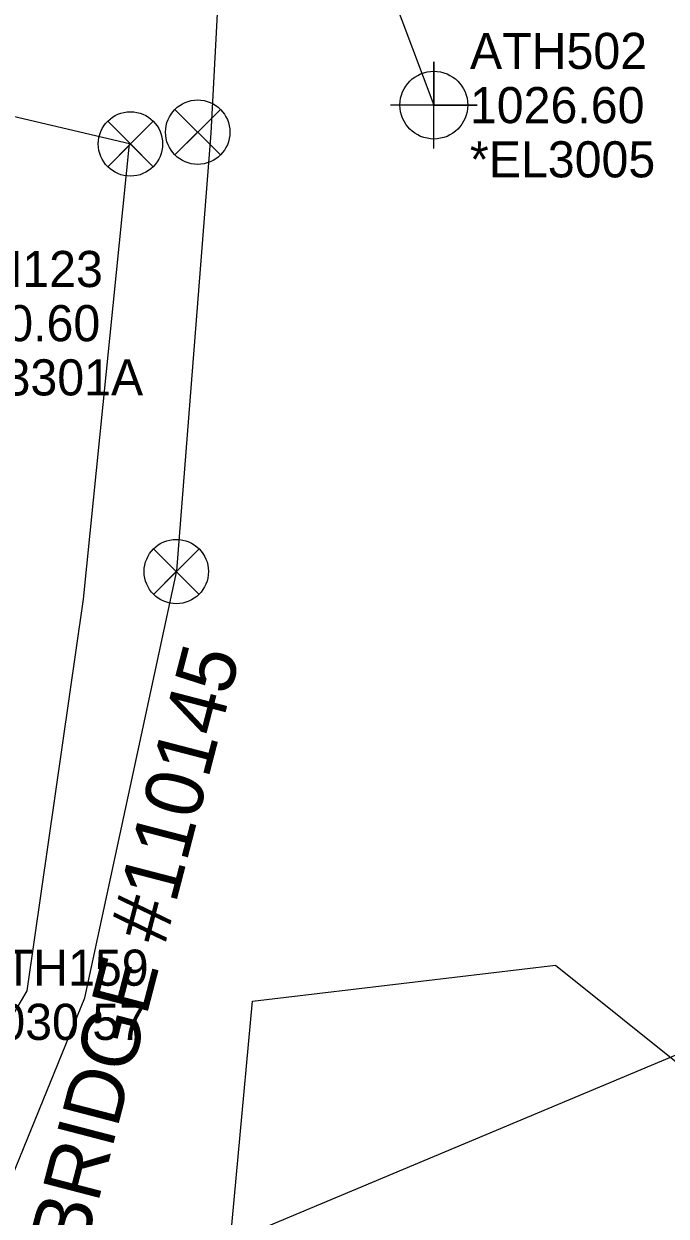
# Model space of a CAD drawing. Extents: x 1212084 to 1214478, y 765637 to 767408.
# Drawn here: x 1213372.2 to 1213416.6, y 766500.6 to 766583.1 of the extents above; entities that cross this region are included whole.
import ezdxf

# ---------------------------------------------------------------- set-up
doc = ezdxf.new("R2010")
doc.units = 0
for name, color, linetype in [('Exist Guardrail Cogo Comment', 7, 'Continuous'), ('Exist Guardrail Cogo Elevation', 7, 'Continuous'), ('Exist Guardrail Cogo Number', 7, 'Continuous'), ('Exist Roads Soil', 7, 'Continuous'), ('Exist Roads Soil Cogo Comment', 7, 'Continuous'), ('Exist Roads Soil Cogo Elevation', 7, 'Continuous'), ('Exist Roads Soil Cogo Number', 7, 'Continuous'), ('Exist Roads Soil Cogo Point CELL', 7, 'Continuous'), ('Exist Structure Major Deck Tunnel Box Culvert Text', 7, 'Continuous'), ('Exist Utilities Other Located Object Text', 7, 'Continuous'), ('Exist Utilities Telephone Pole Cogo Elevation', 7, 'Continuous'), ('Exist Utilities Telephone Pole Cogo Number', 7, 'Continuous'), ('Exist Utilities Water UG Line SUE LOS B', 7, 'Continuous'), ('Exist Utilities Water Valve CELL', 7, 'Continuous'), ('Exist Vegetation Woods Line', 7, 'Continuous')]:
    doc.layers.add(name, color=color, linetype=linetype)

msp = doc.modelspace()

# ---------------------------------------------------------------- linework, layer by layer
at = {"layer": 'Exist Roads Soil'}
msp.add_lwpolyline([(1213379.085, 766618.493), (1213384.449, 766620.241), (1213400.548, 766577.453)], dxfattribs=at)
at = {"layer": 'Exist Roads Soil Cogo Point CELL'}
msp.add_lwpolyline([(1213400.548, 766574.453), (1213400.548, 766580.453), (1213400.548, 766577.453), (1213403.548, 766577.453), (1213397.548, 766577.453)], dxfattribs=at)
msp.add_circle((1213400.548, 766577.453), 2.344, dxfattribs=at)
at = {"layer": 'Exist Utilities Other Located Object Text'}
msp.add_line((1213357.472, 766486.673), (1213475.622, 766536.167), dxfattribs=at)
at = {"layer": 'Exist Utilities Water UG Line SUE LOS B'}
for points in [[(1213442.485, 766187.899), (1213413.61, 766239.451), (1213383.654, 766291.968), (1213352.36, 766345.759), (1213337.483, 766385.325), (1213335.947, 766431.182), (1213343.643, 766467.236), (1213372.392, 766516.172), (1213376.297, 766543.269), (1213379.468, 766574.764), (1213363.657, 766578.488), (1213343.259, 766583.25), (1213356.595, 766631.997), (1213369.551, 766678.004), (1213389.41, 766743.157), (1213404.898, 766797.922), (1213408.97, 766818.968)], [(1213312.252, 766356.682), (1213342.315, 766369.143), (1213353.998, 766372.079), (1213350.927, 766383.418), (1213347.777, 766424.606), (1213351.576, 766454.854), (1213376.387, 766515.679), (1213382.751, 766545.226), (1213385.129, 766575.512), (1213387.127, 766612.966), (1213395.365, 766676.737), (1213413.112, 766741.363), (1213427.394, 766793.323), (1213430.959, 766811.701)]]:
    msp.add_lwpolyline(points, dxfattribs=at)
at = {"layer": 'Exist Utilities Water Valve CELL'}
for points in [[(1213385.776, 766577.157), (1213382.626, 766574.007), (1213384.201, 766575.582), (1213385.776, 766574.007), (1213382.626, 766577.157)], [(1213381.121, 766576.341), (1213377.971, 766573.191), (1213379.546, 766574.766), (1213381.121, 766573.191), (1213377.971, 766576.341)], [(1213384.295, 766546.755), (1213381.145, 766543.605), (1213382.72, 766545.18), (1213384.295, 766543.605), (1213381.145, 766546.755)]]:
    msp.add_lwpolyline(points, dxfattribs=at)
for centre in [(1213384.201, 766575.582), (1213379.546, 766574.766), (1213382.72, 766545.18)]:
    msp.add_circle(centre, 2.227, dxfattribs=at)
at = {"layer": 'Exist Vegetation Woods Line'}
msp.add_lwpolyline([(1213374.017, 766477.977), (1213386.003, 766493.965), (1213388.001, 766515.449), (1213408.977, 766517.947), (1213441.439, 766491.966), (1213442.438, 766435.008), (1213441.439, 766410.526), (1213451.927, 766416.022)], dxfattribs=at)

# ---------------------------------------------------------------- texts
at = {"layer": 'Exist Guardrail Cogo Comment'}
msp.add_text('*BL3301A', height=2.5, dxfattribs=at).set_placement((1213365.37, 766557.366))
at = {"layer": 'Exist Guardrail Cogo Elevation'}
msp.add_text('1030.60', height=2.5, dxfattribs=at).set_placement((1213365.37, 766561.116))
at = {"layer": 'Exist Guardrail Cogo Number'}
msp.add_text('ATH123', height=2.5, dxfattribs=at).set_placement((1213365.37, 766564.866))
at = {"layer": 'Exist Roads Soil Cogo Comment'}
msp.add_text('*EL3005', height=2.5, dxfattribs=at).set_placement((1213403.048, 766572.453))
at = {"layer": 'Exist Roads Soil Cogo Elevation'}
msp.add_text('1026.60', height=2.5, dxfattribs=at).set_placement((1213403.048, 766576.203))
at = {"layer": 'Exist Roads Soil Cogo Number'}
msp.add_text('ATH502', height=2.5, dxfattribs=at).set_placement((1213403.048, 766579.953))
at = {"layer": 'Exist Structure Major Deck Tunnel Box Culvert Text'}
msp.add_text('BRIDGE #110145', height=4, rotation=75.42683, dxfattribs=at).set_placement((1213376.386, 766497.968))
at = {"layer": 'Exist Utilities Telephone Pole Cogo Elevation'}
msp.add_text('1030.57', height=2.5, dxfattribs=at).set_placement((1213368.539, 766512.775))
at = {"layer": 'Exist Utilities Telephone Pole Cogo Number'}
msp.add_text('ATH159', height=2.5, dxfattribs=at).set_placement((1213368.539, 766516.525))

doc.saveas('drawing.dxf')
